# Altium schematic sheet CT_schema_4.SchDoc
size 298 x 247 mm
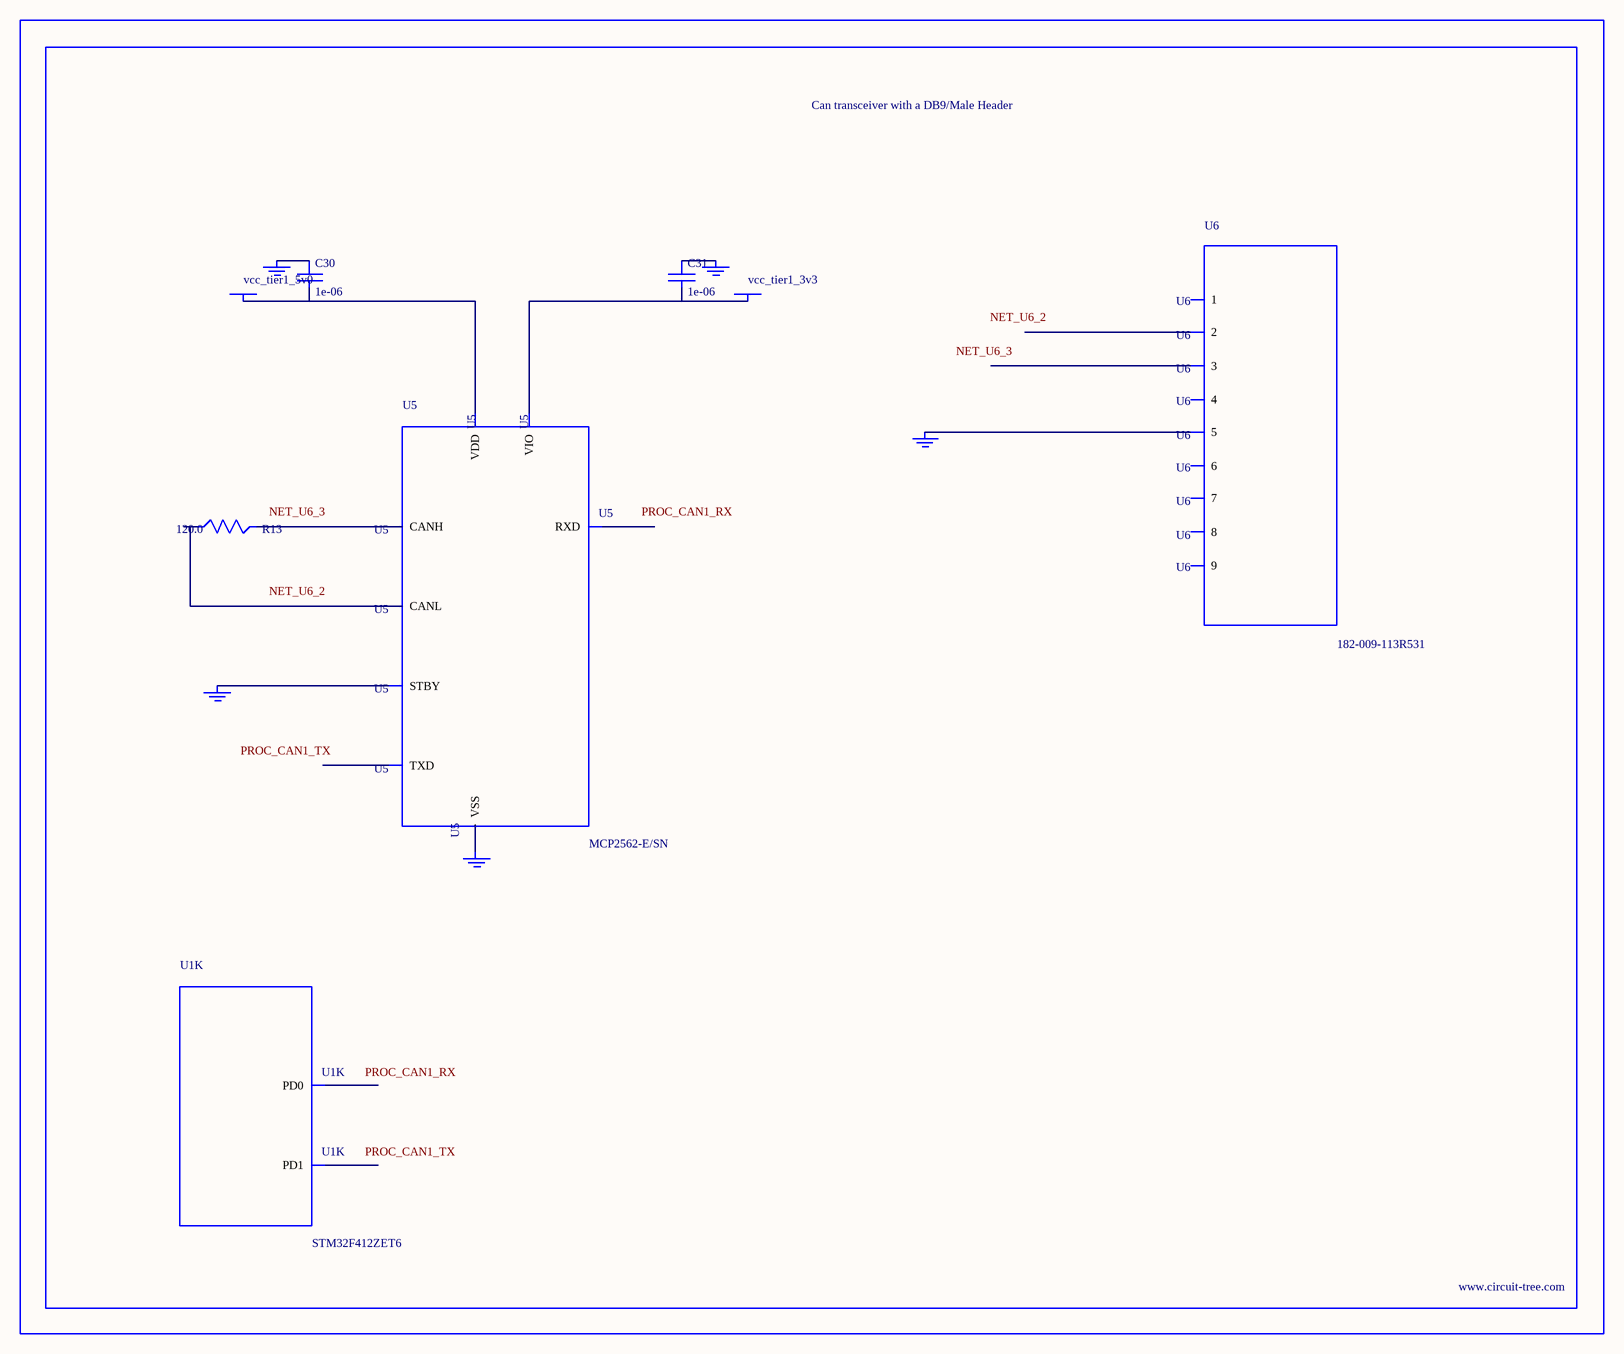
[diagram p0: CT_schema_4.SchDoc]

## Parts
BORDER3  (no value)
C30  1e-06  [C0603]
C31  1e-06  [C0603]
GND_INSTANCE_3_0  (no value)
GND_INSTANCE_3_1  (no value)
GND_INSTANCE_3_2  (no value)
GND_INSTANCE_3_3  (no value)
GND_INSTANCE_3_4  (no value)
POWER_INSTANCE_3_0  vcc_tier1_5v0
POWER_INSTANCE_3_1  vcc_tier1_3v3
R13  120.0  [R0603]
U1  STM32F412ZET6  [LQFP144]  (part K of 13)
U5  MCP2562-E/SN  [SOIC-8]
U6  182-009-113R531  [182-009-MALE]

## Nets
NetC30_1: C30.1 GND_INSTANCE_3_0.0(GND)
NetC30_2: C30.2 POWER_INSTANCE_3_0.0(PWR) U5.3(VDD)
NetC31_1: C31.1 GND_INSTANCE_3_1.0(GND)
NetC31_2: C31.2 POWER_INSTANCE_3_1.0(PWR) U5.5(VIO)
NetGND_INSTANCE_3_2_0: GND_INSTANCE_3_2.0(GND) U5.8(STBY)
NetGND_INSTANCE_3_3_0: GND_INSTANCE_3_3.0(GND) U5.2(VSS)
NetGND_INSTANCE_3_4_0: GND_INSTANCE_3_4.0(GND) U6.5
NetR13_1: R13.1 U5.6(CANL)
NetR13_2: R13.2 U5.7(CANH)

Not connected (* = marked no-connect by the designer): U1 114(PD0) 115(PD1); U5 1(TXD) 4(RXD); U6 1 2 3 4 6 7 8 9

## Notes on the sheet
- Labels drawn without touching a wire or pin: NET_U6_2, NET_U6_3, PROC_CAN1_RX, PROC_CAN1_TX

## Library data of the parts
BORDER3 = BORDER_PAGE3
C30 C31 = C0603C105K3RACTU
GND_INSTANCE_3_0-GND_INSTANCE_3_4 = GND
POWER_INSTANCE_3_0 POWER_INSTANCE_3_1 = PWR
R13 = RC0603JR-07120RL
